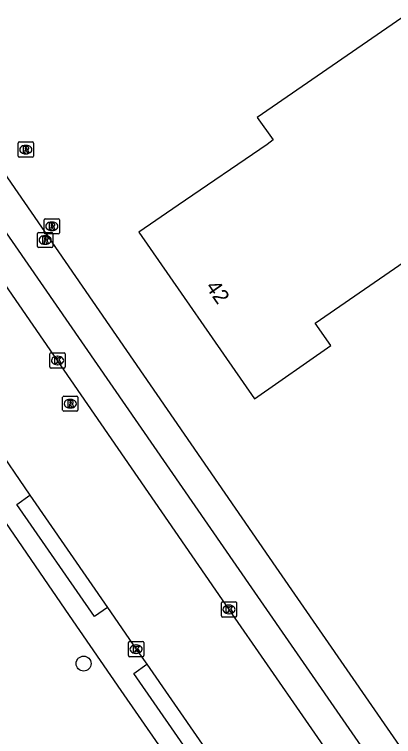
# Model space of a CAD drawing. Extents: x 157466 to 158888, y 383063 to 384677.
# Drawn here: x 157891.49 to 157916.35, y 383361.3 to 383408.68 of the extents above; entities that cross this region are included whole.
import ezdxf

# ---------------------------------------------------------------- set-up
doc = ezdxf.new("R2010")
doc.units = 0
for name, color, linetype in [('IMGEO_Boom', 7, 'Continuous'), ('IMGEO_Kolk', 7, 'Continuous'), ('IMGEO_Pand', 7, 'Continuous'), ('IMGEO_Pand_nummerreeks', 7, 'Continuous'), ('IMGEO_Rijbaan_lokaal_open', 7, 'Continuous'), ('IMGEO_Rioolput', 7, 'Continuous'), ('IMGEO_Voetpad_open', 7, 'Continuous')]:
    doc.layers.add(name, color=color, linetype=linetype)

msp = doc.modelspace()

# ---------------------------------------------------------------- linework, layer by layer
at = {"layer": 'IMGEO_Boom'}
msp.add_circle((157896.026, 383366.088), 0.489, dxfattribs=at)
at = {"layer": 'IMGEO_Kolk'}
for p, q in [((157893.896, 383386.474), (157894.748, 383386.474)), ((157893.821, 383385.548), (157893.821, 383386.4)), ((157894.309, 383386.254), (157894.334, 383386.254)), ((157894.822, 383386.4), (157894.822, 383385.548)), ((157894.332, 383385.694), (157894.307, 383385.694)), ((157894.748, 383385.474), (157893.896, 383385.474)), ((157905.065, 383369.213), (157905.065, 383370.065)), ((157905.14, 383370.139), (157905.992, 383370.139)), ((157905.553, 383369.919), (157905.578, 383369.919)), ((157906.066, 383370.065), (157906.066, 383369.213)), ((157905.992, 383369.139), (157905.14, 383369.139)), ((157905.576, 383369.359), (157905.551, 383369.359)), ((157899.044, 383367.533), (157899.896, 383367.533)), ((157898.969, 383366.607), (157898.969, 383367.459)), ((157899.457, 383367.313), (157899.482, 383367.313)), ((157899.97, 383367.459), (157899.97, 383366.607)), ((157899.48, 383366.753), (157899.455, 383366.753)), ((157899.896, 383366.533), (157899.044, 383366.533))]:
    msp.add_line(p, q, dxfattribs=at)
for points in [[(157893.896, 383386.474), (157894.748, 383386.474)], [(157893.821, 383385.548), (157893.821, 383386.4)], [(157894.142, 383386.174), (157894.265, 383386.174), (157894.265, 383386.023), (157894.395, 383386.174), (157894.559, 383386.174), (157894.413, 383386.023), (157894.566, 383385.774), (157894.414, 383385.774), (157894.329, 383385.938), (157894.265, 383385.871), (157894.265, 383385.774), (157894.142, 383385.774), (157894.142, 383386.174)], [(157894.822, 383386.4), (157894.822, 383385.548)], [(157894.748, 383385.474), (157893.896, 383385.474)], [(157905.065, 383369.213), (157905.065, 383370.065)], [(157905.14, 383370.139), (157905.992, 383370.139)], [(157906.066, 383370.065), (157906.066, 383369.213)], [(157905.386, 383369.839), (157905.509, 383369.839), (157905.509, 383369.688), (157905.639, 383369.839), (157905.803, 383369.839), (157905.657, 383369.688), (157905.81, 383369.439), (157905.658, 383369.439), (157905.573, 383369.603), (157905.509, 383369.536), (157905.509, 383369.439), (157905.386, 383369.439), (157905.386, 383369.839)], [(157905.992, 383369.139), (157905.14, 383369.139)], [(157899.044, 383367.533), (157899.896, 383367.533)], [(157898.969, 383366.607), (157898.969, 383367.459)], [(157899.29, 383367.233), (157899.413, 383367.233), (157899.413, 383367.082), (157899.543, 383367.233), (157899.707, 383367.233), (157899.561, 383367.082), (157899.714, 383366.833), (157899.562, 383366.833), (157899.477, 383366.997), (157899.413, 383366.93), (157899.413, 383366.833), (157899.29, 383366.833), (157899.29, 383367.233)], [(157899.97, 383367.459), (157899.97, 383366.607)], [(157899.896, 383366.533), (157899.044, 383366.533)]]:
    msp.add_lwpolyline(points, dxfattribs=at)
for centre, start, end in [((157893.898, 383386.398), 91.552, 178.448), ((157893.898, 383386.398), 91.552, 178.448), ((157894.746, 383386.398), 1.552, 88.448), ((157894.746, 383386.398), 1.552, 88.448), ((157893.898, 383385.55), 181.552, 268.448), ((157893.898, 383385.55), 181.552, 268.448), ((157894.746, 383385.55), 271.552, 358.448), ((157894.746, 383385.55), 271.552, 358.448), ((157905.142, 383370.063), 91.552, 178.448), ((157905.142, 383370.063), 91.552, 178.448), ((157905.99, 383370.063), 1.552, 88.448), ((157905.99, 383370.063), 1.552, 88.448), ((157905.142, 383369.215), 181.552, 268.448), ((157905.142, 383369.215), 181.552, 268.448), ((157905.99, 383369.215), 271.552, 358.448), ((157905.99, 383369.215), 271.552, 358.448), ((157899.046, 383367.457), 91.552, 178.448), ((157899.046, 383367.457), 91.552, 178.448), ((157899.894, 383367.457), 1.552, 88.448), ((157899.894, 383367.457), 1.552, 88.448), ((157899.046, 383366.609), 181.552, 268.448), ((157899.046, 383366.609), 181.552, 268.448), ((157899.894, 383366.609), 271.552, 358.448), ((157899.894, 383366.609), 271.552, 358.448)]:
    msp.add_arc(centre, 0.0765, start, end, dxfattribs=at)
for centre, major_axis, ratio, start_param, end_param in [((157894.308, 383385.974), (-0.387, 0.002), 0.722429, 4.712389, 7.853982), ((157894.333, 383385.974), (-0.39, 0.002), 0.717154, 1.570796, 4.712389), ((157905.552, 383369.639), (-0.387, 0.002), 0.722429, 4.712389, 7.853982), ((157905.577, 383369.639), (-0.39, 0.002), 0.717154, 1.570796, 4.712389), ((157899.456, 383367.033), (-0.387, 0.002), 0.722429, 4.712389, 7.853982), ((157899.481, 383367.033), (-0.39, 0.002), 0.717154, 1.570796, 4.712389)]:
    msp.add_ellipse(centre, major_axis=major_axis, ratio=ratio, start_param=start_param, end_param=end_param, dxfattribs=at)
at = {"layer": 'IMGEO_Pand'}
msp.add_lwpolyline([(157902.227, 383396.156), (157899.661, 383394.383), (157907.242, 383383.461), (157912.239, 383386.961), (157911.205, 383388.427), (157930.346, 383401.615), (157922.797, 383412.539), (157907.409, 383401.914), (157908.45, 383400.44), (157908.065, 383400.134), (157902.227, 383396.156)], dxfattribs=at)
at = {"layer": 'IMGEO_Rijbaan_lokaal_open'}
for points in [[(157936.465, 383325.145), (157935.643, 383326.174), (157935.388, 383326.53), (157915.623, 383355.122), (157905.565, 383369.639), (157894.321, 383385.972), (157880.805, 383405.562), (157871.979, 383418.406), (157863.862, 383430.224), (157863.215, 383431.182)], [(157889.899, 383380.858), (157890.097, 383380.63), (157892.494, 383377.128)], [(157892.494, 383377.128), (157897.603, 383369.765)], [(157897.603, 383369.765), (157899.471, 383367.034), (157900.174, 383366.038)], [(157900.174, 383366.038), (157907.035, 383356.127)]]:
    msp.add_lwpolyline(points, dxfattribs=at)
at = {"layer": 'IMGEO_Rioolput'}
for p, q in [((157891.737, 383399.383), (157891.737, 383400.235)), ((157891.812, 383400.309), (157892.664, 383400.309)), ((157892.738, 383400.235), (157892.738, 383399.383)), ((157892.225, 383400.089), (157892.25, 383400.089)), ((157892.664, 383399.309), (157891.812, 383399.309)), ((157892.248, 383399.529), (157892.223, 383399.529)), ((157893.441, 383394.351), (157893.441, 383395.203)), ((157893.516, 383395.277), (157894.368, 383395.277)), ((157893.929, 383395.057), (157893.954, 383395.057)), ((157894.442, 383395.203), (157894.442, 383394.351)), ((157893.004, 383393.452), (157893.004, 383394.304)), ((157893.079, 383394.378), (157893.931, 383394.378)), ((157893.492, 383394.158), (157893.517, 383394.158)), ((157894.368, 383394.277), (157893.516, 383394.277)), ((157893.952, 383394.497), (157893.927, 383394.497)), ((157894.005, 383394.304), (157894.005, 383393.452)), ((157893.515, 383393.598), (157893.49, 383393.598)), ((157893.931, 383393.378), (157893.079, 383393.378)), ((157894.73, 383383.638), (157895.582, 383383.638)), ((157894.655, 383382.712), (157894.655, 383383.564)), ((157895.143, 383383.418), (157895.168, 383383.418)), ((157895.656, 383383.564), (157895.656, 383382.712)), ((157895.166, 383382.858), (157895.141, 383382.858)), ((157895.582, 383382.638), (157894.73, 383382.638))]:
    msp.add_line(p, q, dxfattribs=at)
for points in [[(157891.737, 383399.383), (157891.737, 383400.235)], [(157891.812, 383400.309), (157892.664, 383400.309)], [(157892.738, 383400.235), (157892.738, 383399.383)], [(157892.326, 383400.007), (157892.074, 383400.009), (157892.074, 383399.609)], [(157892.074, 383399.609), (157892.198, 383399.609), (157892.198, 383399.771), (157892.209, 383399.771)], [(157892.252, 383399.928), (157892.198, 383399.928), (157892.198, 383399.847)], [(157892.198, 383399.847), (157892.25, 383399.847)], [(157892.256, 383399.742), (157892.327, 383399.609), (157892.467, 383399.609), (157892.402, 383399.735)], [(157892.664, 383399.309), (157891.812, 383399.309)], [(157893.441, 383394.351), (157893.441, 383395.203)], [(157893.516, 383395.277), (157894.368, 383395.277)], [(157894.03, 383394.975), (157893.778, 383394.977), (157893.778, 383394.577)], [(157894.442, 383395.203), (157894.442, 383394.351)], [(157893.778, 383394.577), (157893.902, 383394.577), (157893.902, 383394.739), (157893.913, 383394.739)], [(157893.956, 383394.896), (157893.902, 383394.896), (157893.902, 383394.815)], [(157893.902, 383394.815), (157893.954, 383394.815)], [(157893.96, 383394.71), (157894.031, 383394.577), (157894.171, 383394.577), (157894.106, 383394.703)], [(157893.004, 383393.452), (157893.004, 383394.304)], [(157893.079, 383394.378), (157893.931, 383394.378)], [(157893.593, 383394.076), (157893.341, 383394.078), (157893.341, 383393.678)], [(157894.368, 383394.277), (157893.516, 383394.277)], [(157894.005, 383394.304), (157894.005, 383393.452)], [(157893.341, 383393.678), (157893.465, 383393.678), (157893.465, 383393.84), (157893.476, 383393.84)], [(157893.519, 383393.997), (157893.465, 383393.997), (157893.465, 383393.916)], [(157893.465, 383393.916), (157893.517, 383393.916)], [(157893.523, 383393.811), (157893.594, 383393.678), (157893.734, 383393.678), (157893.669, 383393.804)], [(157893.931, 383393.378), (157893.079, 383393.378)], [(157894.73, 383383.638), (157895.582, 383383.638)], [(157894.655, 383382.712), (157894.655, 383383.564)], [(157895.244, 383383.336), (157894.992, 383383.338), (157894.992, 383382.938)], [(157895.17, 383383.257), (157895.116, 383383.257), (157895.116, 383383.176)], [(157895.116, 383383.176), (157895.168, 383383.176)], [(157895.656, 383383.564), (157895.656, 383382.712)], [(157894.992, 383382.938), (157895.116, 383382.938), (157895.116, 383383.1), (157895.127, 383383.1)], [(157895.174, 383383.071), (157895.245, 383382.938), (157895.385, 383382.938), (157895.32, 383383.064)], [(157895.582, 383382.638), (157894.73, 383382.638)]]:
    msp.add_lwpolyline(points, dxfattribs=at)
for centre, radius, start, end in [((157891.814, 383400.233), 0.0765, 91.552, 178.448), ((157891.814, 383400.233), 0.0765, 91.552, 178.448), ((157892.662, 383400.233), 0.0765, 1.552, 88.448), ((157892.662, 383400.233), 0.0765, 1.552, 88.448), ((157892.208, 383399.718), 0.0533, 26.0293, 88.6989), ((157892.234, 383400.036), 0.19, 274.7715, 282.9687), ((157892.258, 383399.832), 0.0964, 77.0061, 93.1865), ((157892.272, 383399.889), 0.0378, 276.6634, 79.6772), ((157892.325, 383399.897), 0.109, 350.3612, 89.416), ((157892.323, 383399.897), 0.112, 277.5842, 350.9817), ((157892.307, 383399.682), 0.108, 29.5134, 73.7905), ((157891.814, 383399.385), 0.0765, 181.552, 268.448), ((157891.814, 383399.385), 0.0765, 181.552, 268.448), ((157892.662, 383399.385), 0.0765, 271.552, 358.448), ((157892.662, 383399.385), 0.0765, 271.552, 358.448), ((157893.518, 383395.201), 0.0765, 91.552, 178.448), ((157893.518, 383395.201), 0.0765, 91.552, 178.448), ((157894.029, 383394.865), 0.109, 350.3612, 89.416), ((157894.366, 383395.201), 0.0765, 1.552, 88.448), ((157894.366, 383395.201), 0.0765, 1.552, 88.448), ((157893.912, 383394.686), 0.0533, 26.0293, 88.6989), ((157893.938, 383395.004), 0.19, 274.7715, 282.9687), ((157893.962, 383394.8), 0.0964, 77.0061, 93.1865), ((157893.976, 383394.857), 0.0378, 276.6634, 79.6772), ((157894.027, 383394.865), 0.112, 277.5842, 350.9817), ((157894.011, 383394.65), 0.108, 29.5134, 73.7905), ((157893.081, 383394.302), 0.0765, 91.552, 178.448), ((157893.081, 383394.302), 0.0765, 91.552, 178.448), ((157893.518, 383394.353), 0.0765, 181.552, 268.448), ((157893.518, 383394.353), 0.0765, 181.552, 268.448), ((157893.592, 383393.966), 0.109, 350.3612, 89.416), ((157893.929, 383394.302), 0.0765, 1.552, 88.448), ((157893.929, 383394.302), 0.0765, 1.552, 88.448), ((157894.366, 383394.353), 0.0765, 271.552, 358.448), ((157894.366, 383394.353), 0.0765, 271.552, 358.448), ((157893.475, 383393.787), 0.0533, 26.0293, 88.6989), ((157893.501, 383394.105), 0.19, 274.7715, 282.9687), ((157893.525, 383393.901), 0.0964, 77.0061, 93.1865), ((157893.539, 383393.958), 0.0378, 276.6634, 79.6772), ((157893.59, 383393.966), 0.112, 277.5842, 350.9817), ((157893.574, 383393.751), 0.108, 29.5134, 73.7905), ((157893.081, 383393.454), 0.0765, 181.552, 268.448), ((157893.081, 383393.454), 0.0765, 181.552, 268.448), ((157893.929, 383393.454), 0.0765, 271.552, 358.448), ((157893.929, 383393.454), 0.0765, 271.552, 358.448), ((157894.732, 383383.562), 0.0765, 91.552, 178.448), ((157894.732, 383383.562), 0.0765, 91.552, 178.448), ((157895.58, 383383.562), 0.0765, 1.552, 88.448), ((157895.58, 383383.562), 0.0765, 1.552, 88.448), ((157895.152, 383383.365), 0.19, 274.7715, 282.9687), ((157895.176, 383383.161), 0.0964, 77.0061, 93.1865), ((157895.19, 383383.218), 0.0378, 276.6634, 79.6772), ((157895.243, 383383.226), 0.109, 350.3612, 89.416), ((157895.241, 383383.226), 0.112, 277.5842, 350.9817), ((157894.732, 383382.714), 0.0765, 181.552, 268.448), ((157894.732, 383382.714), 0.0765, 181.552, 268.448), ((157895.126, 383383.047), 0.0533, 26.0293, 88.6989), ((157895.225, 383383.011), 0.108, 29.5134, 73.7905), ((157895.58, 383382.714), 0.0765, 271.552, 358.448), ((157895.58, 383382.714), 0.0765, 271.552, 358.448)]:
    msp.add_arc(centre, radius, start, end, dxfattribs=at)
for centre, major_axis, ratio, start_param, end_param in [((157892.224, 383399.809), (-0.387, 0.002), 0.722429, 4.712389, 7.853982), ((157892.249, 383399.809), (-0.39, 0.002), 0.717154, 1.570796, 4.712389), ((157893.928, 383394.777), (-0.387, 0.002), 0.722429, 4.712389, 7.853982), ((157893.953, 383394.777), (-0.39, 0.002), 0.717154, 1.570796, 4.712389), ((157893.491, 383393.878), (-0.387, 0.002), 0.722429, 4.712389, 7.853982), ((157893.516, 383393.878), (-0.39, 0.002), 0.717154, 1.570796, 4.712389), ((157895.142, 383383.138), (-0.387, 0.002), 0.722429, 4.712389, 7.853982), ((157895.167, 383383.138), (-0.39, 0.002), 0.717154, 1.570796, 4.712389)]:
    msp.add_ellipse(centre, major_axis=major_axis, ratio=ratio, start_param=start_param, end_param=end_param, dxfattribs=at)
at = {"layer": 'IMGEO_Voetpad_open'}
for points in [[(157939.64, 383327.608), (157908.666, 383372.402), (157867.433, 383432.258)], [(157877.163, 383395.127), (157877.384, 383395.064), (157877.36, 383394.852), (157881.344, 383389.058), (157886.267, 383381.935), (157886.385, 383381.901), (157890.311, 383376.164), (157895.075, 383369.235), (157898.462, 383364.319), (157909.683, 383348.132), (157925.669, 383324.951), (157928.425, 383320.955), (157932.838, 383314.613), (157951.478, 383311.189), (157955.59, 383314.069), (157957.186, 383314.977), (157965.542, 383320.73)], [(157890.489, 383394.989), (157907.044, 383371.058), (157936.153, 383328.952)], [(157897.603, 383369.765), (157896.749, 383369.172), (157891.64, 383376.535), (157892.494, 383377.128)], [(157907.035, 383356.127), (157906.18, 383355.535), (157899.319, 383365.446), (157900.174, 383366.038)]]:
    msp.add_lwpolyline(points, dxfattribs=at)

# ---------------------------------------------------------------- texts
at = {"layer": 'IMGEO_Pand_nummerreeks'}
msp.add_text('42', height=1, rotation=304.7623, dxfattribs=at).set_placement((157903.996, 383390.804))

doc.saveas('drawing.dxf')
